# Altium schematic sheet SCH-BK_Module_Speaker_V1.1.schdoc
size 230 x 148 mm
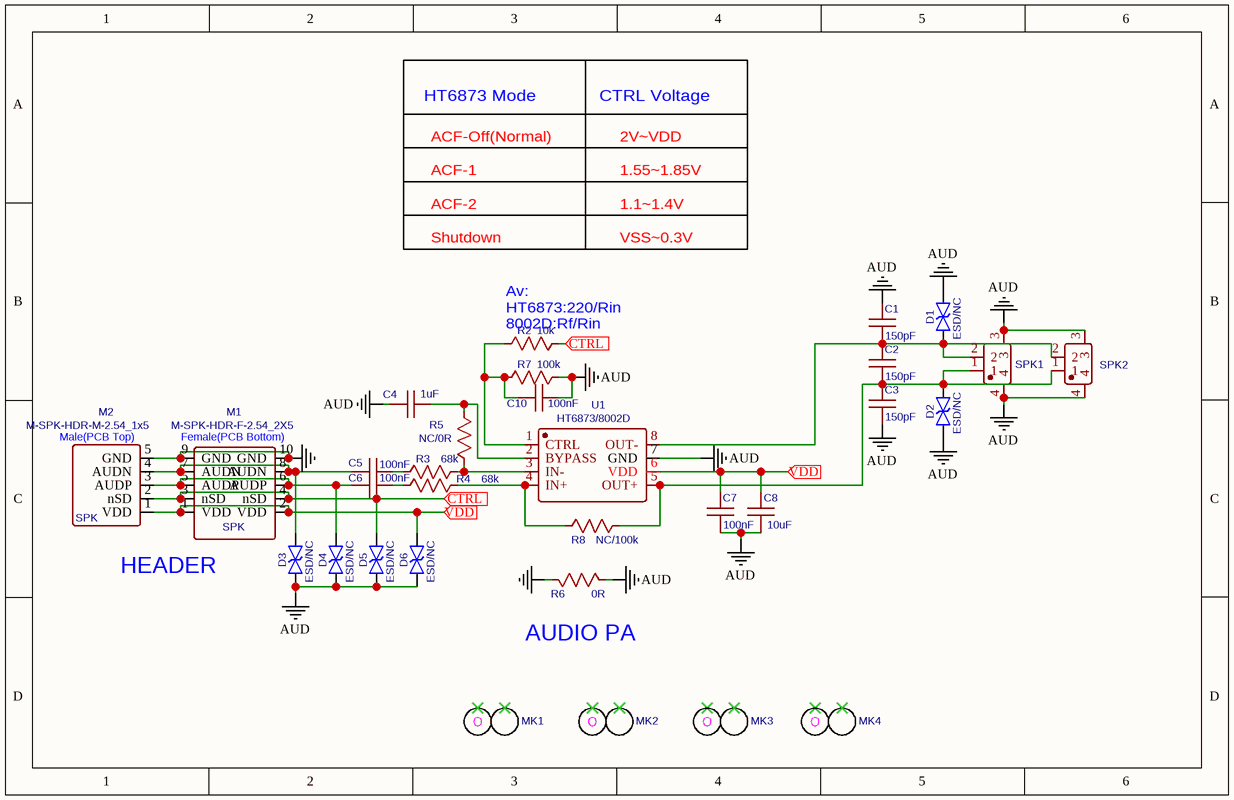
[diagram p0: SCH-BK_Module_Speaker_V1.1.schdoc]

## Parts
C1  150pF  [C0402]
C2  150pF  [C0402]
C3  150pF  [C0402]
C4  1uF  [C0402]
C5  100nF  [C0402]
C6  100nF  [C0402]
C7  100nF  [C0402]
C8  10uF  [C0603]
C10  100nF  [C0402]
D1  ESD/NC  [ESD0402]
D2  ESD/NC  [ESD0402]
D3  ESD/NC  [ESD0402]
D4  ESD/NC  [ESD0402]
D5  ESD/NC  [ESD0402]
D6  ESD/NC  [ESD0402]
M1  M-SPK-HDR-F-2.54_2X5  [M-SPK-HDR-F-2.54_2X5]
M2  M-SPK-HDR-M-2.54_1x5  [M-SPK-HDR-M-2.54_1X5]
MK1  MARK  [MARK]  (value not drawn)
MK2  MARK  [MARK]  (value not drawn)
MK3  MARK  [MARK]  (value not drawn)
MK4  MARK  [MARK]  (value not drawn)
R2  10k  [R0402]
R3  68k  [R0402]
R4  68k  [R0402]
R5  NC/0R  [R0402]
R6  0R  [R0402]
R7  100k  [R0402]
R8  NC/100k  [R0402]
SPK1  喇叭2P-P1.25  [CONN-SMD_2P-P1.25_HCZZ0001-2]  (value not drawn)
SPK2  喇叭2P-P2.0  [CONN-SMD_2P-P2.0_HCZZ0451-2]  (value not drawn)
U1  HT6873/8002D  [SOP-8_L4.9-W3.9-P1.27-LS6.0-BL]

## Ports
CTRL (in), VDD (in)

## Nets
AUD: C1.1 C3.2 C4.2 C7.2 C8.2 C10.1 D1.1 D2.2 D3.2 D4.2 D5.2 D6.2 R6.2 R7.2 SPK1.3 SPK1.4 SPK2.3 SPK2.4 U1.7(GND)
GGND: M1.9(GND) M1.10(GND) M2.5(GND) R6.1
CTRL: D5.1 M1.3(nSD) M1.4(nSD) M2.2(nSD) R2.2 ; port CTRL
VDD: C7.1 C8.1 D6.1 M1.1(VDD) M1.2(VDD) M2.1(VDD) U1.6(VDD) ; port VDD
NetC1_2: C1.2 C2.1 D1.2 SPK1.2 SPK2.2 U1.8(OUT-)
NetC2_2: C2.2 C3.1 D2.1 R8.1 SPK1.1 SPK2.1 U1.5(OUT+)
NetC4_1: C4.1 R5.1 U1.2(BYPASS)
NetC5_1: C5.1 R3.2
NetC5_2: C5.2 D3.1 M1.7(AUDN) M1.8(AUDN) M2.4(AUDN)
NetC6_1: C6.1 R4.2
NetC6_2: C6.2 D4.1 M1.5(AUDP) M1.6(AUDP) M2.3(AUDP)
NetC10_2: C10.2 R2.1 R7.1 U1.1(CTRL)
NetR3_1: R3.1 R5.2 U1.3(IN-)
NetR4_1: R4.1 R8.2 U1.4(IN+)

Not connected (* = marked no-connect by the designer): MK1 1* 2*; MK2 1* 2*; MK3 1* 2*; MK4 1* 2*

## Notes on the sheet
- HT6873 Mode
- ACF-Off(Normal)
- CTRL Voltage
- 2V~VDD
- ACF-1
- ACF-2
- 1.55
  .85V
- 1.1
  .4V
- Shutdown
- Av:
  HT6873:220/Rin
  8002D:Rf/Rin
- VSS~0.3V
- (near M2) Male(PCB Top)
- (near M1) Female(PCB Bottom)
- HEADER
- AUDIO PA

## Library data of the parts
C1-C3 = 150pF: Manufacturer: AVX; Manufacturer Part Number: 0805ZC105KAT2A; APN: C071-0
C4 = 1uF: Manufacturer: AVX; Manufacturer Part Number: 0805ZC105KAT2A; APN: C071-0
C5-C7 = 100nF: Manufacturer: AVX; Manufacturer Part Number: 0805ZC105KAT2A; APN: C071-0
C8 = 10uF: Manufacturer: AVX; Manufacturer Part Number: 0805ZC105KAT2A; APN: C071-0
C10 = 100nF: Manufacturer Part Number: 0805ZC105KAT2A; Manufacturer: AVX; APN: C071-0
D1-D6 = ESD/NC: Contributor: D-MAN
M1 = M-SPK-HDR-F-2.54_2X5: Contributor: qunshan.xu
M2 = M-SPK-HDR-M-2.54_1x5: Contributor: qunshan.xu
MK1-MK4 = MARK: Contributor: qunshan.xu
R2 = 10k: nameAlias: Value(Ω); Contributor: LCEDA_Lib
R3 R4 = 68k: nameAlias: Value(Ω); Contributor: LCEDA_Lib
R5 = NC/0R: nameAlias: Value(Ω); Contributor: LCEDA_Lib
R6 = 0R: nameAlias: Value(Ω); Contributor: LCEDA_Lib
R7 = 100k: nameAlias: Value(Ω); Contributor: LCEDA_Lib
R8 = NC/100k: nameAlias: Value(Ω); Contributor: LCEDA_Lib
SPK1 = 喇叭2P-P1.25: Manufacturer: 虹成电子; Manufacturer Part: HCZZ0001-2; Contributor: LCSC
SPK2 = 喇叭2P-P2.0: Manufacturer: 虹成电子; Manufacturer Part: HCZZ0451-2; Contributor: LCSC
U1 = HT6873/8002D: Manufacturer: 嘉兴禾润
